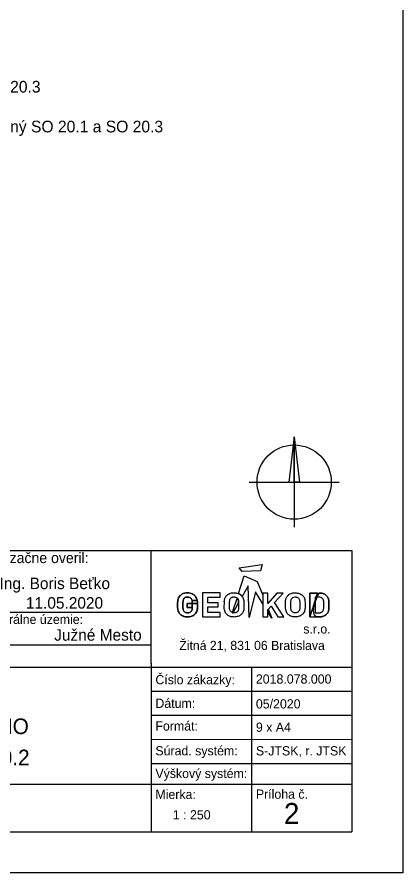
# Model space of a CAD drawing. Extents: x -264165 to -263733, y -1242319 to -1242245.
# Drawn here: x -263754.68 to -263732.86, y -1242319.19 to -1242270.82 of the extents above; entities that cross this region are included whole.
import ezdxf

# ---------------------------------------------------------------- set-up
doc = ezdxf.new("R2010")
doc.units = 0
for name, color, linetype in [('LEGENDA', 7, 'Continuous'), ('RAM_NA_TLAC_1-250', 7, 'Continuous'), ('ROZPISKA', 7, 'Continuous')]:
    doc.layers.add(name, color=color, linetype=linetype)

msp = doc.modelspace()

# ---------------------------------------------------------------- linework, layer by layer
at = {"layer": 'RAM_NA_TLAC_1-250'}
msp.add_lwpolyline([(-264165.363, -1242244.935), (-263732.863, -1242244.935), (-263732.863, -1242319.185), (-264165.363, -1242319.185)], close=True, dxfattribs=at)
at = {"layer": 'ROZPISKA'}
for p, q in [((-263739.011, -1242294.548), (-263739.313, -1242297.099)), ((-263739.011, -1242294.548), (-263739.011, -1242299.649)), ((-263739.011, -1242294.548), (-263738.709, -1242297.098)), ((-263741.561, -1242297.099), (-263736.461, -1242297.098)), ((-263777.719, -1242300.974), (-263735.749, -1242300.973)), ((-263747.091, -1242307.326), (-263747.093, -1242300.973)), ((-263735.749, -1242300.973), (-263735.748, -1242316.856)), ((-263742.16, -1242303.399), (-263741.831, -1242302.403)), ((-263741.831, -1242302.403), (-263741.099, -1242302.713)), ((-263741.099, -1242302.713), (-263740.79, -1242303.499)), ((-263741.621, -1242302.969), (-263741.949, -1242303.556)), ((-263741.557, -1242304.747), (-263741.621, -1242302.969)), ((-263741.206, -1242303.306), (-263741.557, -1242304.747)), ((-263740.79, -1242303.976), (-263741.206, -1242303.306)), ((-263744.483, -1242303.785), (-263744.781, -1242303.785)), ((-263744.781, -1242303.785), (-263744.483, -1242303.785)), ((-263742.241, -1242303.646), (-263742.514, -1242304.474)), ((-263742.427, -1242303.352), (-263742.404, -1242303.351)), ((-263742.422, -1242303.591), (-263742.407, -1242303.591)), ((-263742.422, -1242303.591), (-263742.407, -1242303.591)), ((-263740.504, -1242303.369), (-263740.79, -1242303.369)), ((-263740.79, -1242303.499), (-263740.79, -1242303.976)), ((-263739.986, -1242303.369), (-263740.504, -1242303.956)), ((-263740.504, -1242303.956), (-263740.504, -1242303.369)), ((-263740.122, -1242303.909), (-263739.629, -1242303.369)), ((-263739.629, -1242303.369), (-263739.986, -1242303.369)), ((-263738.119, -1242303.372), (-263737.69, -1242303.373)), ((-263738.119, -1242304.713), (-263738.119, -1242303.372)), ((-263738.119, -1242303.372), (-263738.119, -1242304.713)), ((-263737.69, -1242303.373), (-263738.119, -1242303.372)), ((-263737.825, -1242303.605), (-263737.825, -1242304.48)), ((-263737.825, -1242303.605), (-263737.825, -1242304.48)), ((-263739.602, -1242304.713), (-263740.122, -1242303.909)), ((-263777.721, -1242304.459), (-263747.092, -1242304.459)), ((-263740.279, -1242304.798), (-263740.504, -1242304.437)), ((-263740.48, -1242304.287), (-263740.279, -1242304.798)), ((-263739.94, -1242304.713), (-263739.602, -1242304.713)), ((-263777.72, -1242306.305), (-263747.093, -1242306.305)), ((-263777.723, -1242307.556), (-263747.089, -1242307.552)), ((-263747.091, -1242307.326), (-263747.092, -1242311.411)), ((-263747.089, -1242307.552), (-263735.748, -1242307.552)), ((-263741.421, -1242307.554), (-263741.42, -1242311.639)), ((-263747.091, -1242308.915), (-263735.749, -1242308.917)), ((-263747.094, -1242310.276), (-263735.748, -1242310.275)), ((-263747.092, -1242311.411), (-263747.092, -1242316.854)), ((-263747.094, -1242311.637), (-263735.747, -1242311.639)), ((-263741.42, -1242311.639), (-263741.419, -1242316.855)), ((-263747.092, -1242312.999), (-263735.747, -1242312.997)), ((-263777.72, -1242314.178), (-263735.748, -1242314.176)), ((-263777.72, -1242316.856), (-263735.748, -1242316.856))]:
    msp.add_line(p, q, dxfattribs=at)
for points in [[(-263739.011, -1242294.548), (-263738.709, -1242297.098), (-263739.011, -1242297.098)], [(-263742.122, -1242301.94), (-263740.822, -1242301.753), (-263740.913, -1242302.124), (-263741.949, -1242302.157)], [(-263744.188, -1242303.362), (-263744.188, -1242304.713), (-263743.199, -1242304.713), (-263743.199, -1242304.475), (-263743.892, -1242304.475), (-263743.892, -1242304.151), (-263743.3, -1242304.151), (-263743.3, -1242303.916), (-263743.892, -1242303.916), (-263743.892, -1242303.602), (-263743.199, -1242303.602), (-263743.199, -1242303.362)]]:
    msp.add_lwpolyline(points, close=True, dxfattribs=at)
for points in [[(-263742.152, -1242303.92), (-263742.153, -1242303.891), (-263742.153, -1242303.853), (-263742.157, -1242303.82), (-263742.162, -1242303.787), (-263742.17, -1242303.757), (-263742.182, -1242303.724), (-263742.2, -1242303.692), (-263742.219, -1242303.667), (-263742.241, -1242303.646)], [(-263741.949, -1242303.556), (-263741.958, -1242303.544), (-263741.975, -1242303.525), (-263741.993, -1242303.508), (-263742.012, -1242303.49), (-263742.032, -1242303.475), (-263742.054, -1242303.459), (-263742.073, -1242303.447), (-263742.093, -1242303.434), (-263742.117, -1242303.42), (-263742.138, -1242303.408), (-263742.16, -1242303.399)], [(-263740.79, -1242303.369), (-263740.79, -1242304.713), (-263740.504, -1242304.713), (-263740.504, -1242304.311), (-263740.313, -1242304.11), (-263739.94, -1242304.713)], [(-263744.771, -1242304.183), (-263745.053, -1242304.183), (-263745.053, -1242303.96), (-263744.48, -1242303.96)], [(-263744.48, -1242303.96), (-263745.053, -1242303.96), (-263745.053, -1242304.183), (-263744.771, -1242304.183)], [(-263742.468, -1242304.486), (-263742.152, -1242303.92)], [(-263742.514, -1242304.474), (-263742.507, -1242304.476), (-263742.498, -1242304.479), (-263742.49, -1242304.481), (-263742.481, -1242304.483), (-263742.474, -1242304.485), (-263742.468, -1242304.486)], [(-263740.504, -1242304.437), (-263740.504, -1242304.311), (-263740.48, -1242304.287)]]:
    msp.add_lwpolyline(points, dxfattribs=at)
msp.add_circle((-263739.011, -1242297.099), 2.1, dxfattribs=at)
for points in [[(-263744.48, -1242303.96), (-263744.479, -1242304.13), (-263744.483, -1242304.283), (-263744.514, -1242304.419), (-263744.58, -1242304.528), (-263744.68, -1242304.62), (-263744.785, -1242304.681), (-263744.925, -1242304.716), (-263745.052, -1242304.725), (-263745.183, -1242304.716), (-263745.314, -1242304.672), (-263745.428, -1242304.598), (-263745.515, -1242304.511), (-263745.572, -1242304.392), (-263745.598, -1242304.261), (-263745.603, -1242304.174), (-263745.603, -1242303.907), (-263745.594, -1242303.763), (-263745.554, -1242303.641), (-263745.489, -1242303.536), (-263745.358, -1242303.431), (-263745.218, -1242303.369), (-263745.056, -1242303.352), (-263744.886, -1242303.365), (-263744.706, -1242303.439), (-263744.566, -1242303.571), (-263744.483, -1242303.785), (-263744.48, -1242303.96), (-263744.483, -1242303.785)], [(-263744.483, -1242303.785), (-263744.566, -1242303.571), (-263744.706, -1242303.439), (-263744.886, -1242303.365), (-263745.056, -1242303.352), (-263745.218, -1242303.369), (-263745.358, -1242303.431), (-263745.489, -1242303.536), (-263745.554, -1242303.641), (-263745.594, -1242303.763), (-263745.603, -1242303.907), (-263745.603, -1242304.174), (-263745.598, -1242304.261), (-263745.572, -1242304.392), (-263745.515, -1242304.511), (-263745.428, -1242304.598), (-263745.314, -1242304.672), (-263745.183, -1242304.716), (-263745.052, -1242304.725), (-263744.925, -1242304.716), (-263744.785, -1242304.681), (-263744.68, -1242304.62), (-263744.58, -1242304.528), (-263744.514, -1242304.419), (-263744.483, -1242304.283), (-263744.479, -1242304.13), (-263744.48, -1242303.96), (-263744.483, -1242303.785), (-263744.48, -1242303.96)], [(-263744.779, -1242303.785), (-263744.808, -1242303.711), (-263744.873, -1242303.639), (-263744.963, -1242303.597), (-263745.052, -1242303.591), (-263745.142, -1242303.602), (-263745.214, -1242303.643), (-263745.267, -1242303.7), (-263745.293, -1242303.761), (-263745.295, -1242303.853), (-263745.302, -1242303.954), (-263745.304, -1242304.074), (-263745.302, -1242304.216), (-263745.291, -1242304.321), (-263745.251, -1242304.404), (-263745.195, -1242304.452), (-263745.127, -1242304.48), (-263745.055, -1242304.489), (-263744.969, -1242304.485), (-263744.88, -1242304.448), (-263744.816, -1242304.386), (-263744.779, -1242304.317), (-263744.77, -1242304.236), (-263744.771, -1242304.183), (-263744.779, -1242303.785), (-263744.771, -1242304.183)], [(-263744.771, -1242304.183), (-263744.77, -1242304.236), (-263744.779, -1242304.317), (-263744.816, -1242304.386), (-263744.88, -1242304.448), (-263744.969, -1242304.485), (-263745.055, -1242304.489), (-263745.127, -1242304.48), (-263745.195, -1242304.452), (-263745.251, -1242304.404), (-263745.291, -1242304.321), (-263745.302, -1242304.216), (-263745.304, -1242304.074), (-263745.302, -1242303.954), (-263745.295, -1242303.853), (-263745.293, -1242303.761), (-263745.267, -1242303.7), (-263745.214, -1242303.643), (-263745.142, -1242303.602), (-263745.052, -1242303.591), (-263744.963, -1242303.597), (-263744.873, -1242303.639), (-263744.808, -1242303.711), (-263744.779, -1242303.785), (-263744.771, -1242304.183), (-263744.779, -1242303.785)], [(-263742.404, -1242303.351), (-263742.397, -1242303.351), (-263742.356, -1242303.35), (-263742.281, -1242303.368), (-263742.179, -1242303.386), (-263742.083, -1242303.438), (-263741.997, -1242303.498), (-263741.925, -1242303.582), (-263741.884, -1242303.676), (-263741.858, -1242303.779), (-263741.859, -1242303.942), (-263741.854, -1242304.11), (-263741.858, -1242304.274), (-263741.872, -1242304.379), (-263741.911, -1242304.465), (-263741.961, -1242304.542), (-263742.029, -1242304.601), (-263742.102, -1242304.654), (-263742.193, -1242304.691), (-263742.292, -1242304.719), (-263742.398, -1242304.726), (-263742.499, -1242304.72), (-263742.589, -1242304.712), (-263742.665, -1242304.677), (-263742.738, -1242304.635), (-263742.808, -1242304.59), (-263742.87, -1242304.524), (-263742.921, -1242304.436), (-263742.956, -1242304.33), (-263742.971, -1242304.154), (-263742.956, -1242303.99), (-263742.965, -1242303.833), (-263742.95, -1242303.743), (-263742.931, -1242303.655), (-263742.887, -1242303.577), (-263742.831, -1242303.513), (-263742.77, -1242303.456), (-263742.693, -1242303.415), (-263742.606, -1242303.376), (-263742.514, -1242303.357), (-263742.452, -1242303.353), (-263742.427, -1242303.352)], [(-263742.407, -1242303.591), (-263742.394, -1242303.591), (-263742.363, -1242303.592), (-263742.309, -1242303.603), (-263742.25, -1242303.635), (-263742.197, -1242303.686), (-263742.164, -1242303.761), (-263742.15, -1242303.844), (-263742.152, -1242303.936), (-263742.15, -1242304.031), (-263742.153, -1242304.129), (-263742.148, -1242304.221), (-263742.162, -1242304.298), (-263742.179, -1242304.367), (-263742.223, -1242304.429), (-263742.287, -1242304.471), (-263742.356, -1242304.489), (-263742.412, -1242304.486), (-263742.463, -1242304.489), (-263742.517, -1242304.476), (-263742.57, -1242304.443), (-263742.621, -1242304.394), (-263742.656, -1242304.321), (-263742.668, -1242304.233), (-263742.664, -1242304.127), (-263742.667, -1242304.008), (-263742.664, -1242303.895), (-263742.661, -1242303.802), (-263742.646, -1242303.729), (-263742.606, -1242303.669), (-263742.551, -1242303.624), (-263742.486, -1242303.595), (-263742.441, -1242303.592), (-263742.422, -1242303.591)], [(-263742.407, -1242303.591), (-263742.394, -1242303.591), (-263742.363, -1242303.592), (-263742.309, -1242303.603), (-263742.25, -1242303.635), (-263742.197, -1242303.686), (-263742.164, -1242303.761), (-263742.15, -1242303.844), (-263742.152, -1242303.936), (-263742.15, -1242304.031), (-263742.153, -1242304.129), (-263742.148, -1242304.221), (-263742.162, -1242304.298), (-263742.179, -1242304.367), (-263742.223, -1242304.429), (-263742.287, -1242304.471), (-263742.356, -1242304.489), (-263742.412, -1242304.486), (-263742.463, -1242304.489), (-263742.517, -1242304.476), (-263742.57, -1242304.443), (-263742.621, -1242304.394), (-263742.656, -1242304.321), (-263742.668, -1242304.233), (-263742.664, -1242304.127), (-263742.667, -1242304.008), (-263742.664, -1242303.895), (-263742.661, -1242303.802), (-263742.646, -1242303.729), (-263742.606, -1242303.669), (-263742.551, -1242303.624), (-263742.486, -1242303.595), (-263742.441, -1242303.592), (-263742.422, -1242303.591)], [(-263738.943, -1242303.351), (-263739.042, -1242303.358), (-263739.148, -1242303.381), (-263739.236, -1242303.417), (-263739.307, -1242303.459), (-263739.369, -1242303.514), (-263739.422, -1242303.576), (-263739.466, -1242303.657), (-263739.489, -1242303.745), (-263739.501, -1242303.83), (-263739.5, -1242303.924), (-263739.504, -1242304.215), (-263739.492, -1242304.323), (-263739.453, -1242304.443), (-263739.402, -1242304.528), (-263739.349, -1242304.584), (-263739.273, -1242304.637), (-263739.204, -1242304.676), (-263739.131, -1242304.706), (-263739.041, -1242304.719), (-263738.944, -1242304.724), (-263738.829, -1242304.715), (-263738.727, -1242304.687), (-263738.646, -1242304.653), (-263738.566, -1242304.597), (-263738.504, -1242304.54), (-263738.455, -1242304.468), (-263738.416, -1242304.376), (-263738.4, -1242304.282), (-263738.395, -1242304.164), (-263738.398, -1242303.885), (-263738.402, -1242303.777), (-263738.425, -1242303.68), (-263738.471, -1242303.581), (-263738.534, -1242303.507), (-263738.63, -1242303.436), (-263738.718, -1242303.392), (-263738.822, -1242303.367), (-263738.923, -1242303.351), (-263738.943, -1242303.351), (-263738.943, -1242303.351), (-263738.943, -1242303.351)], [(-263738.946, -1242303.591), (-263739.018, -1242303.597), (-263739.09, -1242303.627), (-263739.145, -1242303.673), (-263739.18, -1242303.726), (-263739.198, -1242303.8), (-263739.203, -1242303.881), (-263739.205, -1242304.003), (-263739.205, -1242304.141), (-263739.205, -1242304.236), (-263739.191, -1242304.321), (-263739.154, -1242304.395), (-263739.106, -1242304.443), (-263739.055, -1242304.473), (-263738.998, -1242304.487), (-263738.952, -1242304.487), (-263738.905, -1242304.487), (-263738.832, -1242304.468), (-263738.76, -1242304.42), (-263738.723, -1242304.367), (-263738.703, -1242304.3), (-263738.691, -1242304.224), (-263738.691, -1242304.137), (-263738.69, -1242304.028), (-263738.691, -1242303.929), (-263738.692, -1242303.85), (-263738.709, -1242303.753), (-263738.74, -1242303.69), (-263738.793, -1242303.637), (-263738.855, -1242303.604), (-263738.908, -1242303.593), (-263738.946, -1242303.591), (-263738.946, -1242303.591), (-263738.946, -1242303.591)], [(-263737.69, -1242303.373), (-263737.55, -1242303.373), (-263737.463, -1242303.377), (-263737.399, -1242303.39), (-263737.316, -1242303.419), (-263737.236, -1242303.464), (-263737.156, -1242303.537), (-263737.097, -1242303.623), (-263737.068, -1242303.702), (-263737.05, -1242303.825), (-263737.049, -1242303.887), (-263737.048, -1242304.154), (-263737.052, -1242304.241), (-263737.058, -1242304.313), (-263737.071, -1242304.389), (-263737.109, -1242304.482), (-263737.176, -1242304.569), (-263737.275, -1242304.647), (-263737.355, -1242304.683), (-263737.437, -1242304.706), (-263737.506, -1242304.713), (-263737.53, -1242304.713), (-263738.119, -1242304.713), (-263737.69, -1242303.373), (-263738.119, -1242304.713)], [(-263738.119, -1242304.713), (-263737.53, -1242304.713), (-263737.506, -1242304.713), (-263737.437, -1242304.706), (-263737.355, -1242304.683), (-263737.275, -1242304.647), (-263737.176, -1242304.569), (-263737.109, -1242304.482), (-263737.071, -1242304.389), (-263737.058, -1242304.313), (-263737.052, -1242304.241), (-263737.048, -1242304.154), (-263737.049, -1242303.887), (-263737.05, -1242303.825), (-263737.068, -1242303.702), (-263737.097, -1242303.623), (-263737.156, -1242303.537), (-263737.236, -1242303.464), (-263737.316, -1242303.419), (-263737.399, -1242303.39), (-263737.463, -1242303.377), (-263737.55, -1242303.373), (-263737.69, -1242303.373), (-263738.119, -1242304.713), (-263737.69, -1242303.373)], [(-263737.825, -1242304.48), (-263737.74, -1242304.481), (-263737.65, -1242304.481), (-263737.557, -1242304.48), (-263737.54, -1242304.481), (-263737.506, -1242304.473), (-263737.452, -1242304.446), (-263737.384, -1242304.398), (-263737.351, -1242304.314), (-263737.34, -1242304.225), (-263737.342, -1242304.098), (-263737.341, -1242303.955), (-263737.342, -1242303.838), (-263737.349, -1242303.759), (-263737.38, -1242303.704), (-263737.439, -1242303.648), (-263737.506, -1242303.618), (-263737.598, -1242303.605), (-263737.66, -1242303.605), (-263737.786, -1242303.606), (-263737.825, -1242303.605)], [(-263737.825, -1242304.48), (-263737.74, -1242304.481), (-263737.65, -1242304.481), (-263737.557, -1242304.48), (-263737.54, -1242304.481), (-263737.506, -1242304.473), (-263737.452, -1242304.446), (-263737.384, -1242304.398), (-263737.351, -1242304.314), (-263737.34, -1242304.225), (-263737.342, -1242304.098), (-263737.341, -1242303.955), (-263737.342, -1242303.838), (-263737.349, -1242303.759), (-263737.38, -1242303.704), (-263737.439, -1242303.648), (-263737.506, -1242303.618), (-263737.598, -1242303.605), (-263737.66, -1242303.605), (-263737.786, -1242303.606), (-263737.825, -1242303.605)]]:
    msp.add_open_spline(points, degree=3, dxfattribs=at)

# ---------------------------------------------------------------- texts
at = {"layer": 'LEGENDA'}
for s, p in [('rozhranie SO 20.1, SO 20.2, SO 20.3', (-263768.001, -1242275.086)), ('susedný / nadväzujúci zrealizovaný SO 20.1 a SO 20.3', (-263768.001, -1242277.336))]:
    msp.add_text(s, height=0.66129, dxfattribs=at).set_placement(p)
at = {"layer": 'ROZPISKA'}
for s, height, rotation, p in [('Autorizačne overil:', 0.59461, 0.0016, (-263757.179, -1242301.678)), ('Ing. Boris Beťko', 0.65241, 0.0456, (-263755.669, -1242303.151)), ('11.05.2020', 0.652, 0.0456, (-263754.18, -1242304.255)), ('Katastrálne územie:', 0.5217, 0.0016, (-263757.115, -1242305.117)), ('Južné Mesto', 0.65241, 0.0456, (-263752.581, -1242306.064)), ('s.r.o.', 0.5173, 0.0016, (-263738.492, -1242305.658)), ('Žitná 21, 831 06 Bratislava', 0.51728, 0.0016, (-263745.507, -1242306.59)), ('Číslo zákazky:', 0.52157, 0.0016, (-263746.858, -1242308.527)), ('Dátum:', 0.5217, 0.0016, (-263746.858, -1242309.862)), ('DOKUMENTÁCIA SKUTOČNÉHO', 0.88076, 0.0456, (-263772.141, -1242311.355)), ('Formát:', 0.5217, 0.0016, (-263746.858, -1242311.144)), ('Súrad. systém:', 0.52157, 0.0016, (-263746.858, -1242312.544)), ('VYHOTOVENIA STAVBY SO 20.2', 0.88076, 0.0456, (-263772.101, -1242313.116)), ('Výškový systém:', 0.52156, 0.0016, (-263746.858, -1242313.826)), ('Príloha č.', 0.5216, 0.0016, (-263741.176, -1242314.994)), ('Mierka:', 0.5217, 0.0016, (-263746.858, -1242315.01))]:
    msp.add_text(s, height=height, rotation=rotation, dxfattribs=at).set_placement(p)
for s, height, p in [('2018.078.000', 0.52245, (-263741.176, -1242308.49)), ('05/2020', 0.5224, (-263741.176, -1242309.894)), ('9 x A4', 0.5224, (-263741.176, -1242311.213)), ('S-JTSK, r. JTSK', 0.52245, (-263741.176, -1242312.547)), ('2', 1.176, (-263739.59, -1242316.413)), ('1 : 250', 0.5224, (-263745.873, -1242316.164))]:
    msp.add_text(s, height=height, dxfattribs=at).set_placement(p)

doc.saveas('drawing.dxf')
